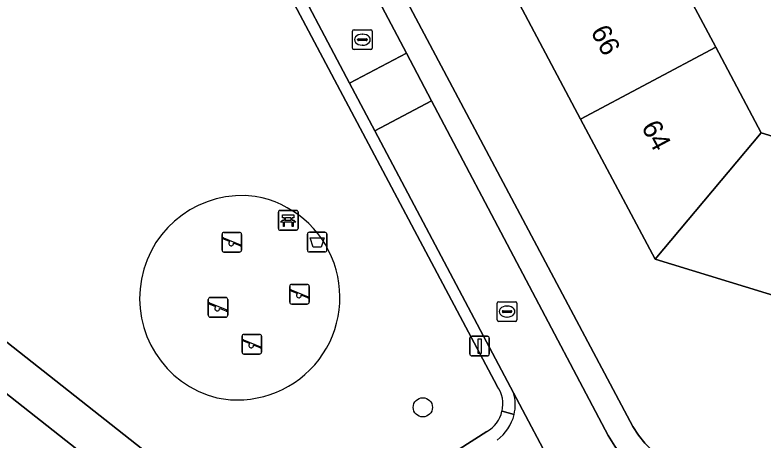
# Model space of a CAD drawing. Extents: x 160304 to 160955, y 383684 to 384161.
# Drawn here: x 160594.82 to 160632.85, y 383811.69 to 383833.3 of the extents above; entities that cross this region are included whole.
import ezdxf

# ---------------------------------------------------------------- set-up
doc = ezdxf.new("R2010")
doc.units = 0
for name, color, linetype in [('IMGEO_Afvalbak', 7, 'Continuous'), ('IMGEO_Bank', 7, 'Continuous'), ('IMGEO_Boom', 7, 'Continuous'), ('IMGEO_Erf', 7, 'Continuous'), ('IMGEO_Groenvoorziening', 7, 'Continuous'), ('IMGEO_Kolk', 7, 'Continuous'), ('IMGEO_Lichtmast', 7, 'Continuous'), ('IMGEO_Pand', 7, 'Continuous'), ('IMGEO_Pand_nummerreeks', 7, 'Continuous'), ('IMGEO_Parkeervlak_open', 7, 'Continuous'), ('IMGEO_Rijbaan_lokaal_open', 7, 'Continuous'), ('IMGEO_Speelvoorziening', 7, 'Continuous'), ('IMGEO_Terreindeel_zand', 7, 'Continuous'), ('IMGEO_Voetpad_halfverhard', 7, 'Continuous'), ('IMGEO_Voetpad_open', 7, 'Continuous')]:
    doc.layers.add(name, color=color, linetype=linetype)

msp = doc.modelspace()

# ---------------------------------------------------------------- linework, layer by layer
at = {"layer": 'IMGEO_Afvalbak'}
for p, q in [((160609.685, 383821.35), (160609.685, 383822.15)), ((160609.685, 383822.15), (160609.685, 383821.35)), ((160609.785, 383822.25), (160610.575, 383822.25)), ((160610.575, 383822.25), (160609.785, 383822.25)), ((160610.675, 383822.15), (160610.675, 383821.35)), ((160610.675, 383821.35), (160610.675, 383822.15)), ((160610.575, 383821.25), (160609.785, 383821.25)), ((160609.785, 383821.25), (160610.575, 383821.25))]:
    msp.add_line(p, q, dxfattribs=at)
msp.add_lwpolyline([(160609.828, 383821.964), (160610.532, 383821.964), (160610.383, 383821.494), (160609.977, 383821.494), (160609.828, 383821.964)], dxfattribs=at)
for centre, start, end in [((160609.785, 383822.15), 90, 180), ((160609.785, 383822.15), 90, 180), ((160610.575, 383822.15), 0, 90), ((160610.575, 383822.15), 360, 90), ((160609.785, 383821.35), 180, 270), ((160609.785, 383821.35), 180, 270), ((160610.575, 383821.35), 270, 0), ((160610.575, 383821.35), 270, 0)]:
    msp.add_arc(centre, 0.1, start, end, dxfattribs=at)
at = {"layer": 'IMGEO_Bank'}
for p, q in [((160608.211, 383822.434), (160608.211, 383823.275)), ((160608.211, 383823.275), (160608.211, 383822.434)), ((160608.286, 383823.359), (160609.127, 383823.359)), ((160609.127, 383823.359), (160608.286, 383823.359)), ((160609.211, 383823.284), (160609.211, 383822.443)), ((160609.211, 383822.443), (160609.211, 383823.284)), ((160608.52, 383822.865), (160608.52, 383822.971)), ((160608.564, 383822.971), (160608.564, 383822.865)), ((160608.852, 383822.977), (160608.57, 383822.977)), ((160608.57, 383822.859), (160608.852, 383822.859)), ((160608.858, 383822.865), (160608.858, 383822.971)), ((160608.902, 383822.971), (160608.902, 383822.865)), ((160608.908, 383822.757), (160608.515, 383822.757)), ((160609.136, 383822.359), (160608.295, 383822.359)), ((160608.295, 383822.359), (160609.136, 383822.359))]:
    msp.add_line(p, q, dxfattribs=at)
for points in [[(160608.458, 383822.757), (160608.316, 383822.757), (160608.428, 383822.859), (160608.514, 383822.859)], [(160608.514, 383822.977), (160608.428, 383822.977), (160608.428, 383823.138), (160608.991, 383823.138), (160608.991, 383822.977), (160608.908, 383822.977)], [(160608.908, 383822.859), (160608.991, 383822.859), (160609.103, 383822.757), (160608.964, 383822.757)], [(160608.508, 383822.75), (160608.508, 383822.543), (160608.465, 383822.543), (160608.465, 383822.75)], [(160608.958, 383822.75), (160608.958, 383822.543), (160608.914, 383822.543), (160608.914, 383822.75)]]:
    msp.add_lwpolyline(points, dxfattribs=at)
for centre, radius, start, end in [((160608.289, 383823.281), 0.0779, 92.4484, 184.2845), ((160608.289, 383823.281), 0.0779, 92.4484, 184.2845), ((160609.133, 383823.281), 0.0779, 2.4484, 94.2845), ((160609.133, 383823.281), 0.0779, 2.4484, 94.2845), ((160608.513, 383822.97), 0.00671, 2.8957, 87.1043), ((160608.513, 383822.866), 0.00671, 272.8957, 357.1043), ((160608.57, 383822.97), 0.00671, 92.8957, 177.1043), ((160608.57, 383822.866), 0.00671, 182.8957, 267.1043), ((160608.852, 383822.97), 0.00671, 2.8957, 87.1043), ((160608.852, 383822.866), 0.00671, 272.8957, 357.1043), ((160608.909, 383822.97), 0.00671, 92.8957, 177.1043), ((160608.909, 383822.866), 0.00671, 182.8957, 267.1043), ((160608.289, 383822.437), 0.0779, 182.4484, 274.2845), ((160608.289, 383822.437), 0.0779, 182.4484, 274.2845), ((160608.458, 383822.75), 0.00671, 2.8957, 87.1043), ((160608.515, 383822.75), 0.00671, 92.8957, 177.1043), ((160608.907, 383822.75), 0.00671, 2.8957, 87.1043), ((160608.964, 383822.75), 0.00671, 92.8957, 177.1043), ((160609.133, 383822.437), 0.0779, 272.4484, 4.2845), ((160609.133, 383822.437), 0.0779, 272.4484, 4.2845)]:
    msp.add_arc(centre, radius, start, end, dxfattribs=at)
at = {"layer": 'IMGEO_Boom'}
msp.add_circle((160615.555, 383813.35), 0.489, dxfattribs=at)
at = {"layer": 'IMGEO_Erf'}
for points in [[(160619.961, 383865.579), (160614.056, 383862.434), (160616.932, 383857.033), (160619.558, 383852.103), (160622.131, 383847.273), (160624.703, 383842.443), (160627.335, 383837.501), (160630.447, 383831.658), (160632.764, 383827.308), (160637.98, 383825.716)], [(160635.725, 383818.327), (160627.376, 383820.875), (160623.58, 383828.002), (160620.464, 383833.854), (160617.836, 383838.787), (160615.265, 383843.616), (160612.692, 383848.446), (160610.063, 383853.384), (160606.586, 383859.913), (160602.222, 383857.561), (160608.312, 383846.103), (160626.241, 383812.373), (160626.527, 383811.938), (160626.85, 383811.531), (160627.209, 383811.154), (160627.6, 383810.811), (160628.02, 383810.504), (160628.465, 383810.236), (160628.933, 383810.009), (160629.419, 383809.824), (160629.92, 383809.684), (160630.04, 383809.657), (160645.643, 383804.913)]]:
    msp.add_lwpolyline(points, dxfattribs=at)
at = {"layer": 'IMGEO_Groenvoorziening'}
for points in [[(160512.051, 383860.483), (160527.152, 383851.99), (160555.752, 383830.697), (160558.345, 383828.766), (160565.781, 383823.661), (160582.534, 383812.776), (160600.019, 383802.155), (160610.062, 383796.203), (160622.299, 383789.443), (160640.34, 383780.06), (160649.742, 383775.545), (160664.695, 383768.884), (160685.542, 383758.679), (160684.972, 383756.649), (160697.446, 383751.712), (160700.343, 383760.526), (160696.112, 383762.451), (160684.565, 383767.367), (160636.545, 383788.535), (160627.316, 383792.767), (160623.864, 383794.407), (160613.532, 383800.088), (160603.749, 383806.669), (160564.231, 383837.826)], [(160619.328, 383814.427), (160604.518, 383842.331), (160604.46, 383842.449), (160604.391, 383842.561), (160604.313, 383842.666), (160604.225, 383842.764), (160604.129, 383842.854), (160604.025, 383842.935), (160603.915, 383843.007), (160603.799, 383843.068), (160603.677, 383843.118), (160603.552, 383843.158), (160603.424, 383843.186), (160603.293, 383843.203), (160603.162, 383843.207), (160603.031, 383843.201), (160602.901, 383843.182), (160602.773, 383843.152), (160602.648, 383843.11), (160602.527, 383843.058), (160602.412, 383842.995), (160602.375, 383842.972), (160598.521, 383840.826), (160593.955, 383849.41)], [(160592.198, 383828.52), (160589.078, 383820.852), (160606.303, 383807.27), (160613.979, 383802.041), (160620.758, 383798.197), (160628.361, 383794.476), (160636.045, 383790.923), (160677.55, 383772.608), (160678.007, 383772.445), (160678.477, 383772.323), (160678.955, 383772.244), (160679.439, 383772.208), (160679.924, 383772.215), (160680.407, 383772.266), (160680.883, 383772.359), (160681.349, 383772.495), (160681.801, 383772.671), (160682.235, 383772.888), (160682.649, 383773.142), (160683.038, 383773.432), (160683.399, 383773.756), (160683.73, 383774.111)], [(160618, 383804.82), (160615.008, 383809.705), (160618.813, 383812.118)]]:
    msp.add_lwpolyline(points, dxfattribs=at)
for centre, radius, start, end in [((160606.381, 383818.893), 5.225, 82.8015, 255.5569), ((160606.125, 383818.942), 5.215, 258.4236, 79.9349), ((160618.11, 383813.522), 1.518, 345.8081, 36.6046), ((160618.029, 383813.503), 1.591, 299.5001, 347.1877)]:
    msp.add_arc(centre, radius, start, end, dxfattribs=at)
at = {"layer": 'IMGEO_Kolk'}
for p, q in [((160611.981, 383831.614), (160611.981, 383832.466)), ((160612.056, 383832.54), (160612.908, 383832.54)), ((160612.982, 383832.466), (160612.982, 383831.614)), ((160612.24, 383832.034), (160612.24, 383832.046)), ((160612.678, 383831.997), (160612.28, 383831.997)), ((160612.283, 383832.083), (160612.681, 383832.083)), ((160612.469, 383832.32), (160612.494, 383832.32)), ((160612.724, 383832.046), (160612.724, 383832.034)), ((160612.492, 383831.76), (160612.467, 383831.76)), ((160612.908, 383831.54), (160612.056, 383831.54)), ((160619.337, 383817.794), (160619.337, 383818.646)), ((160619.412, 383818.72), (160620.264, 383818.72)), ((160620.338, 383818.646), (160620.338, 383817.794)), ((160619.639, 383818.263), (160620.037, 383818.263)), ((160619.825, 383818.5), (160619.85, 383818.5)), ((160619.596, 383818.214), (160619.596, 383818.226)), ((160620.034, 383818.177), (160619.636, 383818.177)), ((160619.848, 383817.94), (160619.823, 383817.94)), ((160620.08, 383818.226), (160620.08, 383818.214)), ((160620.264, 383817.72), (160619.412, 383817.72))]:
    msp.add_line(p, q, dxfattribs=at)
for points in [[(160611.981, 383831.614), (160611.981, 383832.466)], [(160612.056, 383832.54), (160612.908, 383832.54)], [(160612.982, 383832.466), (160612.982, 383831.614)], [(160612.908, 383831.54), (160612.056, 383831.54)], [(160619.337, 383817.794), (160619.337, 383818.646)], [(160619.412, 383818.72), (160620.264, 383818.72)], [(160620.338, 383818.646), (160620.338, 383817.794)], [(160620.264, 383817.72), (160619.412, 383817.72)]]:
    msp.add_lwpolyline(points, dxfattribs=at)
for centre, radius, start, end in [((160612.058, 383832.464), 0.0765, 91.552, 178.448), ((160612.058, 383832.464), 0.0765, 91.552, 178.448), ((160612.906, 383832.464), 0.0765, 1.552, 88.448), ((160612.906, 383832.464), 0.0765, 1.552, 88.448), ((160612.28, 383832.043), 0.0403, 85.8775, 175.7526), ((160612.277, 383832.033), 0.0366, 178.938, 274.7102), ((160612.681, 383832.04), 0.043, 264.8664, 352.4533), ((160612.685, 383832.045), 0.0386, 1.7309, 96.639), ((160612.058, 383831.616), 0.0765, 181.552, 268.448), ((160612.058, 383831.616), 0.0765, 181.552, 268.448), ((160612.906, 383831.616), 0.0765, 271.552, 358.448), ((160612.906, 383831.616), 0.0765, 271.552, 358.448), ((160619.414, 383818.644), 0.0765, 91.552, 178.448), ((160619.414, 383818.644), 0.0765, 91.552, 178.448), ((160620.262, 383818.644), 0.0765, 1.552, 88.448), ((160620.262, 383818.644), 0.0765, 1.552, 88.448), ((160619.636, 383818.223), 0.0403, 85.8775, 175.7526), ((160620.041, 383818.225), 0.0386, 1.7309, 96.639), ((160619.633, 383818.213), 0.0366, 178.938, 274.7102), ((160620.037, 383818.22), 0.043, 264.8664, 352.4533), ((160619.414, 383817.796), 0.0765, 181.552, 268.448), ((160619.414, 383817.796), 0.0765, 181.552, 268.448), ((160620.262, 383817.796), 0.0765, 271.552, 358.448), ((160620.262, 383817.796), 0.0765, 271.552, 358.448)]:
    msp.add_arc(centre, radius, start, end, dxfattribs=at)
for centre, major_axis, ratio, start_param, end_param in [((160612.468, 383832.04), (-0.387, 0.002), 0.722429, 4.712389, 7.853982), ((160612.493, 383832.04), (-0.39, 0.002), 0.717154, 1.570796, 4.712389), ((160619.824, 383818.22), (-0.387, 0.002), 0.722429, 4.712389, 7.853982), ((160619.849, 383818.22), (-0.39, 0.002), 0.717154, 1.570796, 4.712389)]:
    msp.add_ellipse(centre, major_axis=major_axis, ratio=ratio, start_param=start_param, end_param=end_param, dxfattribs=at)
at = {"layer": 'IMGEO_Lichtmast'}
for p, q in [((160617.945, 383816.065), (160617.945, 383816.865)), ((160617.945, 383816.865), (160617.945, 383816.065)), ((160618.045, 383816.965), (160618.835, 383816.965)), ((160618.835, 383816.965), (160618.045, 383816.965)), ((160618.935, 383816.865), (160618.935, 383816.065)), ((160618.935, 383816.065), (160618.935, 383816.865)), ((160618.835, 383815.965), (160618.045, 383815.965)), ((160618.045, 383815.965), (160618.835, 383815.965))]:
    msp.add_line(p, q, dxfattribs=at)
msp.add_lwpolyline([(160618.365, 383816.84), (160618.515, 383816.84), (160618.515, 383816.09), (160618.365, 383816.09), (160618.365, 383816.84)], dxfattribs=at)
for centre, start, end in [((160618.045, 383816.865), 90, 180), ((160618.045, 383816.865), 90, 180), ((160618.835, 383816.865), 0, 90), ((160618.835, 383816.865), 360, 90), ((160618.045, 383816.065), 180, 270), ((160618.045, 383816.065), 180, 270), ((160618.835, 383816.065), 270, 0), ((160618.835, 383816.065), 270, 0)]:
    msp.add_arc(centre, 0.1, start, end, dxfattribs=at)
at = {"layer": 'IMGEO_Pand'}
for points in [[(160630.447, 383831.658), (160627.335, 383837.501), (160620.464, 383833.854), (160623.58, 383828.002)], [(160630.447, 383831.658), (160623.58, 383828.002), (160627.376, 383820.875), (160632.764, 383827.308)], [(160637.98, 383825.716), (160632.764, 383827.308), (160627.376, 383820.875), (160635.725, 383818.327)]]:
    msp.add_lwpolyline(points, close=True, dxfattribs=at)
at = {"layer": 'IMGEO_Parkeervlak_open'}
msp.add_lwpolyline([(160622.284, 383810.088), (160620.166, 383814.09)], dxfattribs=at)
for centre, radius, start, end in [((160618.048, 383813.477), 2.205, 347.0749, 16.1361), ((160618.051, 383813.482), 2.203, 305.4927, 346.9438)]:
    msp.add_arc(centre, radius, start, end, dxfattribs=at)
at = {"layer": 'IMGEO_Rijbaan_lokaal_open'}
for points in [[(160595.869, 383862.983), (160595.697, 383862.746), (160595.505, 383862.526), (160595.294, 383862.323), (160595.066, 383862.14), (160594.822, 383861.978), (160604.871, 383842.991), (160611.835, 383829.832), (160614.718, 383831.355), (160607.23, 383845.532), (160601.204, 383856.942), (160601.168, 383857.1), (160601.049, 383857.809), (160600.993, 383858.527), (160601.001, 383859.246), (160601.074, 383859.962), (160601.21, 383860.668), (160601.409, 383861.36), (160602.642, 383865.533)], [(160627.373, 383805.768), (160632.544, 383804.181), (160639.862, 383801.938), (160648.47, 383799.311), (160649.444, 383802.481), (160642.055, 383804.752), (160629.871, 383808.362), (160629.33, 383808.487), (160628.728, 383808.68), (160628.145, 383808.926), (160627.587, 383809.224), (160627.058, 383809.57), (160626.562, 383809.961), (160626.103, 383810.396), (160625.684, 383810.87), (160625.31, 383811.379), (160624.982, 383811.92), (160616.002, 383828.924), (160613.121, 383827.402), (160620.166, 383814.09), (160622.284, 383810.088)]]:
    msp.add_lwpolyline(points, dxfattribs=at)
msp.add_lwpolyline([(160611.835, 383829.832), (160613.121, 383827.402), (160616.002, 383828.924), (160614.718, 383831.355)], close=True, dxfattribs=at)
at = {"layer": 'IMGEO_Speelvoorziening'}
for p, q in [((160605.345, 383821.345), (160605.345, 383822.145)), ((160605.345, 383822.145), (160605.345, 383821.345)), ((160605.445, 383822.245), (160606.235, 383822.245)), ((160606.235, 383822.245), (160605.445, 383822.245)), ((160606.335, 383822.145), (160606.335, 383821.345)), ((160606.335, 383821.345), (160606.335, 383822.145)), ((160605.728, 383821.773), (160605.389, 383821.91)), ((160605.414, 383821.97), (160606.29, 383821.617)), ((160606.266, 383821.557), (160605.926, 383821.694)), ((160606.235, 383821.245), (160605.445, 383821.245)), ((160605.445, 383821.245), (160606.235, 383821.245)), ((160608.787, 383818.701), (160608.787, 383819.501)), ((160608.787, 383819.501), (160608.787, 383818.701)), ((160608.887, 383819.601), (160609.677, 383819.601)), ((160609.677, 383819.601), (160608.887, 383819.601)), ((160609.777, 383819.501), (160609.777, 383818.701)), ((160609.777, 383818.701), (160609.777, 383819.501)), ((160609.17, 383819.129), (160608.831, 383819.266)), ((160608.856, 383819.326), (160609.732, 383818.973)), ((160609.708, 383818.913), (160609.368, 383819.05)), ((160604.643, 383818.034), (160604.643, 383818.834)), ((160604.643, 383818.834), (160604.643, 383818.034)), ((160604.712, 383818.659), (160605.588, 383818.306)), ((160604.743, 383818.934), (160605.533, 383818.934)), ((160605.533, 383818.934), (160604.743, 383818.934)), ((160605.633, 383818.834), (160605.633, 383818.034)), ((160605.633, 383818.034), (160605.633, 383818.834)), ((160605.026, 383818.462), (160604.687, 383818.599)), ((160605.564, 383818.246), (160605.224, 383818.383)), ((160609.677, 383818.601), (160608.887, 383818.601)), ((160608.887, 383818.601), (160609.677, 383818.601)), ((160605.533, 383817.934), (160604.743, 383817.934)), ((160604.743, 383817.934), (160605.533, 383817.934)), ((160606.362, 383816.16), (160606.362, 383816.96)), ((160606.362, 383816.96), (160606.362, 383816.16)), ((160606.431, 383816.785), (160607.307, 383816.432)), ((160606.462, 383817.06), (160607.252, 383817.06)), ((160607.252, 383817.06), (160606.462, 383817.06)), ((160607.352, 383816.96), (160607.352, 383816.16)), ((160607.352, 383816.16), (160607.352, 383816.96)), ((160606.745, 383816.588), (160606.406, 383816.725)), ((160607.283, 383816.372), (160606.943, 383816.509)), ((160607.252, 383816.06), (160606.462, 383816.06)), ((160606.462, 383816.06), (160607.252, 383816.06))]:
    msp.add_line(p, q, dxfattribs=at)
for centre, radius, start, end in [((160605.445, 383822.145), 0.1, 90, 180), ((160605.445, 383822.145), 0.1, 90, 180), ((160606.235, 383822.145), 0.1, 0, 90), ((160606.235, 383822.145), 0.1, 360, 90), ((160605.402, 383821.94), 0.0327, 68.078, 248.078), ((160605.807, 383821.683), 0.12, 130.9928, 5.1632), ((160605.445, 383821.345), 0.1, 180, 270), ((160605.445, 383821.345), 0.1, 180, 270), ((160606.235, 383821.345), 0.1, 270, 0), ((160606.235, 383821.345), 0.1, 270, 0), ((160606.278, 383821.587), 0.0327, 248.078, 68.078), ((160608.887, 383819.501), 0.1, 90, 180), ((160608.887, 383819.501), 0.1, 90, 180), ((160609.677, 383819.501), 0.1, 0, 90), ((160609.677, 383819.501), 0.1, 360, 90), ((160608.844, 383819.296), 0.0327, 68.078, 248.078), ((160609.249, 383819.039), 0.12, 130.9928, 5.1632), ((160604.743, 383818.834), 0.1, 90, 180), ((160604.743, 383818.834), 0.1, 90, 180), ((160604.7, 383818.629), 0.0327, 68.078, 248.078), ((160605.533, 383818.834), 0.1, 0, 90), ((160605.533, 383818.834), 0.1, 360, 90), ((160608.887, 383818.701), 0.1, 180, 270), ((160608.887, 383818.701), 0.1, 180, 270), ((160609.677, 383818.701), 0.1, 270, 0), ((160609.677, 383818.701), 0.1, 270, 0), ((160609.72, 383818.943), 0.0327, 248.078, 68.078), ((160605.105, 383818.372), 0.12, 130.9928, 5.1632), ((160605.576, 383818.276), 0.0327, 248.078, 68.078), ((160604.743, 383818.034), 0.1, 180, 270), ((160604.743, 383818.034), 0.1, 180, 270), ((160605.533, 383818.034), 0.1, 270, 0), ((160605.533, 383818.034), 0.1, 270, 0), ((160606.462, 383816.96), 0.1, 90, 180), ((160606.462, 383816.96), 0.1, 90, 180), ((160606.419, 383816.755), 0.0327, 68.078, 248.078), ((160607.252, 383816.96), 0.1, 0, 90), ((160607.252, 383816.96), 0.1, 360, 90), ((160606.824, 383816.498), 0.12, 130.9928, 5.1632), ((160607.295, 383816.402), 0.0327, 248.078, 68.078), ((160606.462, 383816.16), 0.1, 180, 270), ((160606.462, 383816.16), 0.1, 180, 270), ((160607.252, 383816.16), 0.1, 270, 0), ((160607.252, 383816.16), 0.1, 270, 0)]:
    msp.add_arc(centre, radius, start, end, dxfattribs=at)
at = {"layer": 'IMGEO_Terreindeel_zand'}
for centre, radius, start, end in [((160606.381, 383818.893), 5.225, 82.8015, 255.5569), ((160606.125, 383818.942), 5.215, 258.4236, 79.9349)]:
    msp.add_arc(centre, radius, start, end, dxfattribs=at)
at = {"layer": 'IMGEO_Voetpad_halfverhard'}
for points in [[(160587.546, 383868.946), (160567.255, 383845.98), (160567.181, 383845.905), (160566.724, 383845.485), (160566.231, 383845.107), (160565.706, 383844.775), (160565.154, 383844.491), (160564.578, 383844.257), (160563.984, 383844.076), (160563.376, 383843.949), (160564.231, 383837.826), (160603.749, 383806.669), (160613.532, 383800.088), (160623.864, 383794.407), (160627.316, 383792.767), (160636.545, 383788.535), (160684.565, 383767.367)], [(160683.73, 383774.111), (160683.399, 383773.756), (160683.038, 383773.432), (160682.649, 383773.142), (160682.235, 383772.888), (160681.801, 383772.671), (160681.349, 383772.495), (160680.883, 383772.359), (160680.407, 383772.266), (160679.924, 383772.215), (160679.439, 383772.208), (160678.955, 383772.244), (160678.477, 383772.323), (160678.007, 383772.445), (160677.55, 383772.608), (160636.045, 383790.923), (160628.361, 383794.476), (160620.758, 383798.197), (160613.979, 383802.041), (160606.303, 383807.27), (160589.078, 383820.852)]]:
    msp.add_lwpolyline(points, dxfattribs=at)
at = {"layer": 'IMGEO_Voetpad_open'}
for points in [[(160602.642, 383865.533), (160601.409, 383861.36), (160601.21, 383860.668), (160601.074, 383859.962), (160601.001, 383859.246), (160600.993, 383858.527), (160601.049, 383857.809), (160601.168, 383857.1), (160601.204, 383856.942), (160607.23, 383845.532), (160614.718, 383831.355), (160616.002, 383828.924), (160624.982, 383811.92), (160625.31, 383811.379), (160625.684, 383810.87), (160626.103, 383810.396), (160626.562, 383809.961), (160627.058, 383809.57), (160627.587, 383809.224), (160628.145, 383808.926), (160628.728, 383808.68), (160629.33, 383808.487), (160629.871, 383808.362), (160642.055, 383804.752)], [(160687.175, 383797.44), (160683.302, 383798.622), (160681.863, 383793.899), (160647.349, 383804.394), (160645.643, 383804.913), (160630.04, 383809.657), (160629.92, 383809.684), (160629.419, 383809.824), (160628.933, 383810.009), (160628.465, 383810.236), (160628.02, 383810.504), (160627.6, 383810.811), (160627.209, 383811.154), (160626.85, 383811.531), (160626.527, 383811.938), (160626.241, 383812.373), (160608.312, 383846.103), (160602.222, 383857.561), (160606.586, 383859.913), (160605.024, 383862.845)], [(160593.955, 383849.41), (160598.521, 383840.826), (160602.375, 383842.972), (160602.412, 383842.995), (160602.527, 383843.058), (160602.648, 383843.11), (160602.773, 383843.152), (160602.901, 383843.182), (160603.031, 383843.201), (160603.162, 383843.207), (160603.293, 383843.203), (160603.424, 383843.186), (160603.552, 383843.158), (160603.677, 383843.118), (160603.799, 383843.068), (160603.915, 383843.007), (160604.025, 383842.935), (160604.129, 383842.854), (160604.225, 383842.764), (160604.313, 383842.666), (160604.391, 383842.561), (160604.46, 383842.449), (160604.518, 383842.331), (160619.328, 383814.427)], [(160620.166, 383814.09), (160613.121, 383827.402), (160611.835, 383829.832), (160604.871, 383842.991)], [(160620.197, 383812.984), (160619.581, 383813.15)], [(160619.581, 383813.15), (160620.197, 383812.984)], [(160618.813, 383812.118), (160615.008, 383809.705), (160618, 383804.82)]]:
    msp.add_lwpolyline(points, dxfattribs=at)
for centre, radius, start, end in [((160618.11, 383813.522), 1.518, 345.8081, 36.6046), ((160618.048, 383813.477), 2.205, 347.0749, 16.1361), ((160618.029, 383813.503), 1.591, 299.5001, 347.1877), ((160618.051, 383813.482), 2.203, 305.4927, 346.9438)]:
    msp.add_arc(centre, radius, start, end, dxfattribs=at)

# ---------------------------------------------------------------- texts
at = {"layer": 'IMGEO_Pand_nummerreeks'}
for s, rotation, p in [('66', 298.0372, (160624.064, 383832.454)), ('64', 298.042, (160626.645, 383827.609))]:
    msp.add_text(s, height=1, rotation=rotation, dxfattribs=at).set_placement(p)

doc.saveas('drawing.dxf')
